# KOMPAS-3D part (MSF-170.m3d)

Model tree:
1. Ось X
2. Ось Y
3. Ось Z
4. Начало координат  (labels: Операция без истории:1)

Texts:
  Линия-выноска #1
  Линия-выноска #2
  Линия-выноска #3
  Отклонения формы и база
  Марка координационной оси
  Марка/позиционное обозначение с линией-выноской
  Марка/позиционное обозначение на линии
  Марка/позиционное обозначение без линии-выноски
